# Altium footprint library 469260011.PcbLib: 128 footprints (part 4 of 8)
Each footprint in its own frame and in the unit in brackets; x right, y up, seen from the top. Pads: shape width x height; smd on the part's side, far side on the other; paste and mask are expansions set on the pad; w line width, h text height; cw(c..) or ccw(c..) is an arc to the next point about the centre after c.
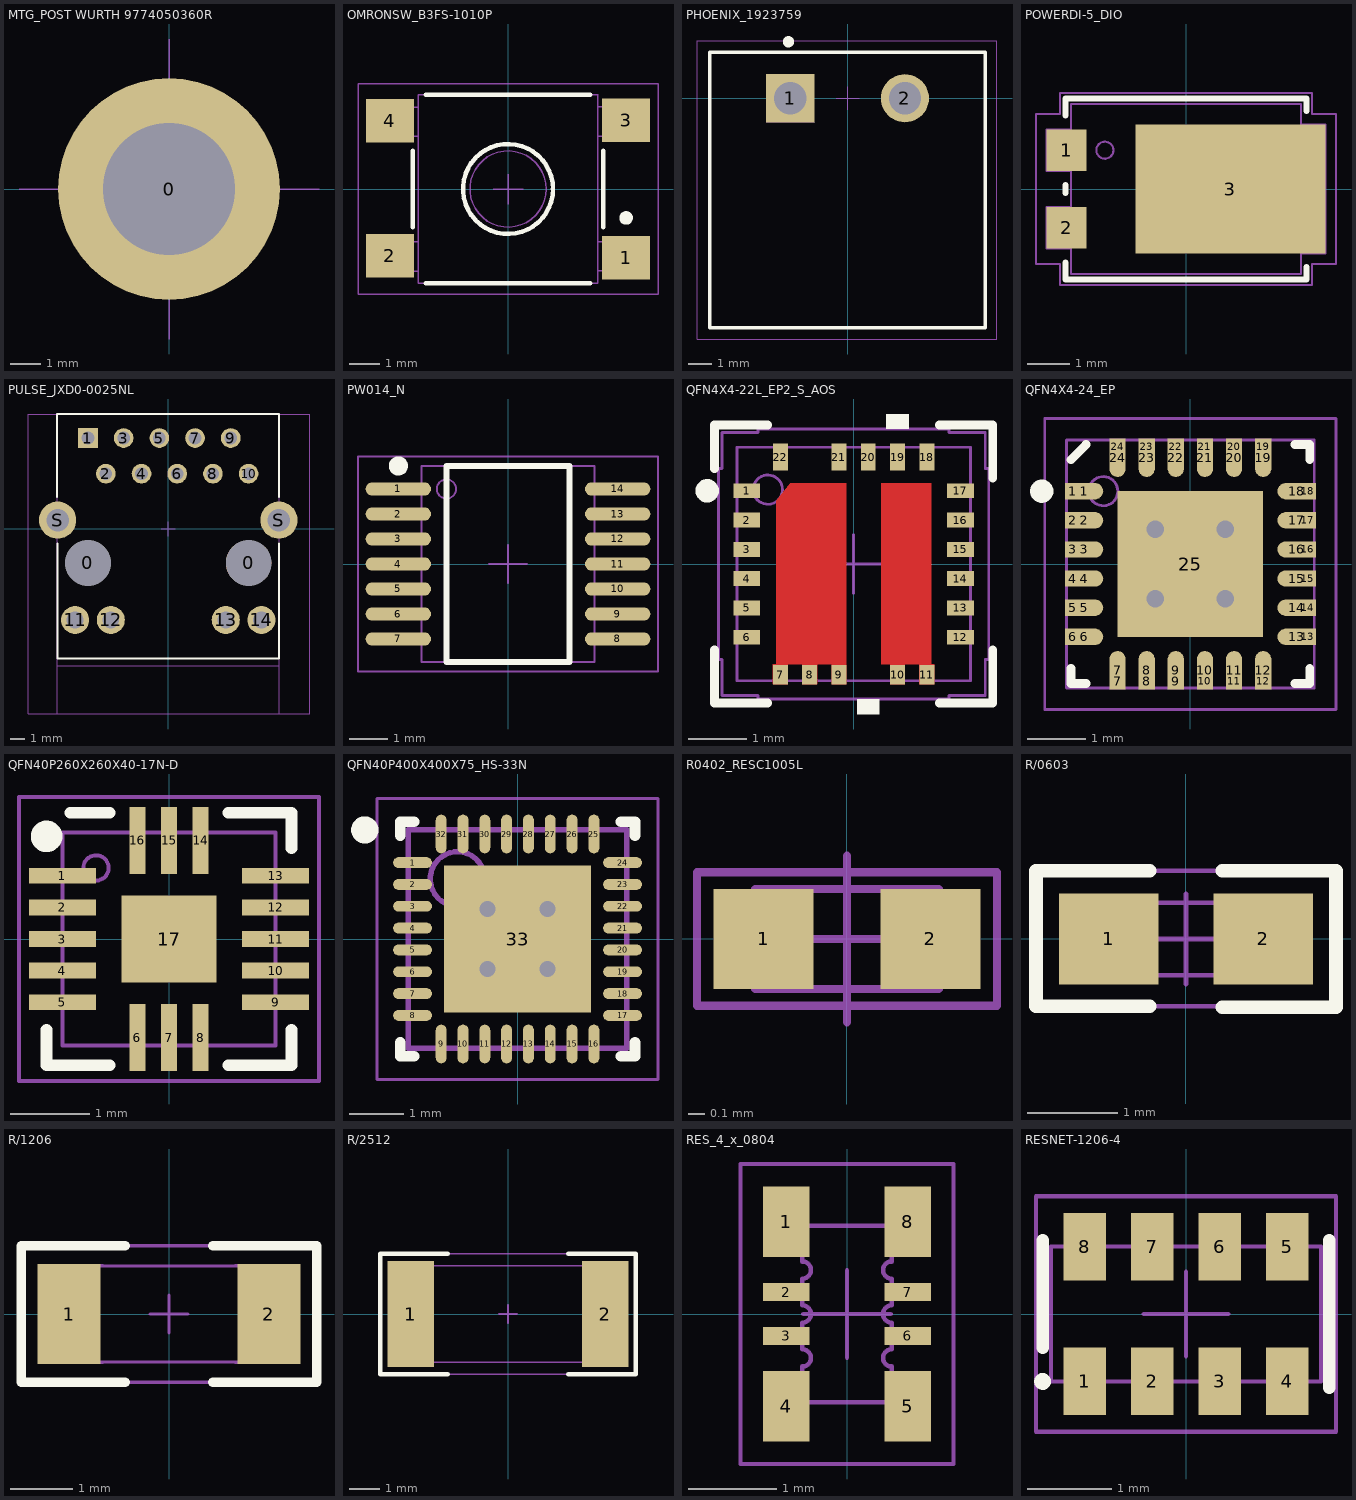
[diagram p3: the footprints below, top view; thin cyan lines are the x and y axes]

## MTG_POST WURTH 9774050360R [mm] "Mounting Post Wurth Electronics 9774050360R"
height 5
pads (1):
  round 7.4 hole 4.4: 0(0,0)
Top Paste:
  region: 3.61,-0.289 3.571,-0.596 3.395,-1.19 3.127,-1.748 2.772,-2.256 2.341,-2.7 1.844,-3.07 1.294,-3.356 0.706,-3.549 0.4,-3.598 0.4,-2.299 0.582,-2.263 0.934,-2.147 1.261,-1.975 1.556,-1.75 1.809,-1.479 2.013,-1.17 2.163,-0.831 2.255,-0.472 2.279,-0.289
  region: 0.4,3.594 0.693,3.548 1.258,3.368 1.79,3.104 2.274,2.761 2.7,2.348 3.057,1.874 3.338,1.351 3.535,0.792 3.589,0.5 2.281,0.5 2.241,0.667 2.123,0.99 1.956,1.291 1.744,1.562 1.494,1.797 1.21,1.991 0.899,2.139 0.569,2.237 0.4,2.266
  region: -3.614,0.25 -3.578,0.56 -3.407,1.162 -3.141,1.728 -2.788,2.243 -2.355,2.694 -1.856,3.07 -1.302,3.36 -0.709,3.557 -0.4,3.607 -0.4,2.299 -0.584,2.263 -0.94,2.145 -1.272,1.968 -1.568,1.738 -1.822,1.462 -2.026,1.147 -2.174,0.802 -2.261,0.437 -2.281,0.25
  region: -0.35,-3.609 -0.647,-3.566 -1.22,-3.39 -1.759,-3.126 -2.25,-2.782 -2.682,-2.367 -3.045,-1.889 -3.329,-1.361 -3.528,-0.795 -3.583,-0.5 -2.275,-0.5 -2.235,-0.671 -2.114,-0.999 -1.944,-1.305 -1.727,-1.58 -1.47,-1.818 -1.179,-2.013 -0.86,-2.159 -0.523,-2.253 -0.35,-2.28
Mechanical 1:
  lines w0.05: -5,0 5,0 ; 0,-5 0,5
3D body "9774050360R (rev1).stp": height 5, standoff -1.4, extent -3,-2.997 2.988,2.997

## OMRONSW_B3FS-1010P [mil] "SWITCH TACTILE SPST-NO 6.30mm x 6.00mm"
height 169.29
pads (4):
  rect 63x57 smd: 1(155,-90) 2(-154.96,-87.6) 3(155,90) 4(-154.96,89.57)
Top Overlay:
  circle w9.84: c155,-38 r3.94
  circle w5.91: c0,0 r59.06
  lines w5.91: -125,-50 -125,50 ; -108.27,-124.02 108.27,-124.02 ; -108.27,124.02 108.27,124.02 ; 125,-50 125,50
Top Assembly:
  circle w1.97: c0.07,0 r50.06
  lines w1.97: -118.11,123.58 -118.11,-124.02 118.11,-124.02 118.11,123.58 ; -118.04,-107.64 -165.28,-107.64 -165.28,-69.36 -118.04,-69.36 ; -118.07,68.93 -165.31,68.93 -165.31,107.2 -118.07,107.2 ; -118.07,123.58 118.15,123.58 ; 118.11,69.36 165.35,69.36 165.35,107.64 118.11,107.64 ; 118.14,-107.2 165.38,-107.2 165.38,-68.93 118.14,-68.93
  text ".Designator" at -88.6,-8.9 h39.37
Top Courtyard:
  lines w1.97: -19.61,0 19.76,0 ; 0,-19.69 0,19.68 ; -196.85,-137.8 -196.85,137.8 196.85,137.8 196.85,-137.8 -196.85,-137.8
3D body "Unnamed-B3FS_1000.step": height 118.11, standoff -3.94, extent -157.41,-124.02 157.55,124.02

## PHOENIX_1923759 [mm] "TERM BLOCK HDR 2POS 90DEG 5MM"
height 8.61
pads (2):
  rect 2.1x2.1 / inner round 2.1 / far side rect 2.1x2.1 hole 1.4: 1(-2.5,0)
  round 2.1 hole 1.4: 2(2.5,0)
Top Overlay:
  circle w0.25: c-2.576,2.464 r0.12
  lines w0.15: -6,-10 -6,2 6,2 6,-10 -6,-10
Top Assembly:
  region: -2.5,0 -1.45,-1.05 -3.55,-1.05
  lines w0.05: -6,-10 -6,2 6,2 6,-10 -6,-10
  text ".Designator" at -2.252,-0.226 h1
Top Courtyard:
  lines w0.05: -0.5,0 0.5,0 ; 0,-0.5 0,0.5 ; -6.55,-10.486 6.5,-10.486 6.5,2.514 -6.55,2.514 -6.55,-10.486
3D body "pxc_1923759_02_MSTBA-2-5-HC-2-G_3D.stp": height 9.14, standoff -2.96, extent -6,-10 6,2

## POWERDI-5_DIO [mil] "Diodes PowerDI5"
height 45.28
pads (3):
  rect 37x39 smd paste+0 mask+0: 1(-111.5,36.22) 2(-111.5,-36.22)
  rect 177x120 smd paste+0 mask+0: 3(41.5,0)
Top Overlay:
  lines w5.91: -112.5,-68.82 -112.5,-84.5 112.5,-84.5 112.5,-73.1 ; -112.5,-3.62 -112.5,3.62 ; -112.5,68.82 -112.5,84.5 112.5,84.5 112.5,73.1
Top 3D Body:
  lines w1: -107.5,-79.5 -107.5,79.5 107.5,79.5 107.5,-79.5 -107.5,-79.5
Top Assembly:
  circle w1.97: c-75.7,36.22 r7.95
  lines w1.97: -107.48,-55.7 -130,-55.7 -130,-16.73 -107.48,-16.73 ; -107.48,16.74 -130,16.74 -130,55.71 -107.48,55.71 ; 107.48,-60 130,-60 130,60 107.48,60 ; -107.48,-79.48 -107.48,79.49 107.48,79.49 107.48,-79.48 -107.48,-79.48
  text ".Designator" at -88.67,-8.9 h39.37
Top Courtyard:
  lines w1.97: -19.68,0 19.69,0 ; 0,-19.69 0,19.68 ; -140,-70 -117.5,-70 -117.5,-89.5 117.5,-89.5 117.5,-70 140,-70 140,70 117.5,70 117.5,89.5 -117.5,89.5 -117.5,70 -140,70 -140,-70
3D body "2x1_POWERDI-5_SBRT10U50SP5_DIO.step": height 45.24, standoff 0, extent -130,-79.49 130,79.49

## PULSE_JXD0-0025NL [mm]
height 13.63
pads (18):
  round 3.25 hole 3.25 unplated: 0(-5.715,-2.415) 0(5.715,-2.415)
  rect 1.4x1.4 hole 0.9: 1(-5.715,6.475)
  round 1.4 hole 0.9: 2(-4.445,3.935) 3(-3.175,6.475) 4(-1.905,3.935) 5(-0.635,6.475) 6(0.635,3.935) 7(1.905,6.475) 8(3.175,3.935) 9(4.445,6.475) 10(5.715,3.935)
  round 2 hole 1.2: 11(-6.63,-6.475) 12(-4.09,-6.475) 13(4.09,-6.475) 14(6.63,-6.475)
  round 2.65 hole 1.6: S(-7.875,0.635) S(7.875,0.635)
Top Overlay:
  lines w0.15: -7.915,2.285 -7.915,8.184 7.885,8.184 7.885,2.285 ; -7.885,-1.043 -7.885,-9.215 7.885,-9.215 7.885,-1.043
Mechanical 1:
  lines w0.05: -7.915,-9.715 7.885,-9.715 ; -7.915,-9.715 -7.915,-13.166 7.885,-13.166 7.885,-9.715 ; -7.915,-9.715 7.885,-9.715 ; -7.915,-9.715 7.885,-9.715
  text "KEEP-OUT" at -4.567,-12.094 h2
Top Assembly:
  lines w0.05: -7.915,-9.715 7.885,-9.715 ; -7.915,-13.166 7.885,-13.166 7.885,8.184 -7.915,8.184 -7.915,-13.166
  text ".Designator" at -2.252,-0.226 h1
Top Courtyard:
  lines w0.05: -0.5,0 0.5,0 ; 0,-0.5 0,0.5 ; -9.949,-13.166 10.051,-13.166 10.051,8.184 -9.949,8.184 -9.949,-13.166
3D body "JXD0-0025NL_3D.STEP": height 15.5, standoff -3.8, extent -9.949,-13.166 10.051,8.184

## PW014_N [mm] "TSOP, 14-Leads, Body 5x4.4mm, Pitch 0.65mm, IPC Medium Density"
height 1.2
pads (14):
  oval 1.7x0.35 smd: 1(-2.85,1.95) 2(-2.85,1.3) 3(-2.85,0.65) 4(-2.85,0) 5(-2.85,-0.65) 6(-2.85,-1.3) 7(-2.85,-1.95) 8(2.85,-1.95) 9(2.85,-1.3) 10(2.85,-0.65) 11(2.85,0) 12(2.85,0.65) 13(2.85,1.3) 14(2.85,1.95)
Top Overlay:
  circle w0.25: c-2.85,2.55 r0.125
  lines w0.15: -1.6,-2.55 -1.6,2.55 1.6,2.55 1.6,-2.55 -1.6,-2.55
Top Assembly:
  circle w0.05: c-1.6,1.95 r0.25
  lines w0.05: -2.25,-2.55 -2.25,2.55 2.25,2.55 2.25,-2.55 -2.25,-2.55
  text ".Designator" at -2.252,-0.226 h1
Top Courtyard:
  lines w0.05: -0.5,0 0.5,0 ; 0,-0.5 0,0.5 ; -3.9,-2.8 -3.9,2.8 3.9,2.8 3.9,-2.8 -3.9,-2.8
3D body "User Library-TSSOP14-1.step": height 1.1, standoff 0, extent -3.19,-2.493 3.21,2.507

## QFN4X4-22L_EP2_S_AOS [mil]
height 39.37
pads (22):
  rect 18x10 smd paste+0 mask+0: 1(-71.85,49.25) 2(-71.85,29.55) 3(-71.85,9.85) 4(-71.85,-9.85) 5(-71.85,-29.55) 6(-71.85,-49.25) 12(71.85,-49.25) 13(71.85,-29.55) 14(71.85,-9.85) 15(71.85,9.85) 16(71.85,29.55) 17(71.85,49.25)
  rect 10x13 smd paste-6.5 mask-6.5: 7(-49.25,-74.35) 8(-29.55,-74.35) 9(-9.85,-74.35) 10(29.55,-74.35) 11(49.25,-74.35)
  rect 10x18 smd paste+0 mask+0: 18(49.25,71.85) 19(29.55,71.85) 20(9.85,71.85) 21(-9.85,71.85) 22(-49.25,71.85)
Top Layer:
  region: 18.55,54.45 18.55,-67.55 24.55,-67.55 24.55,-80.85 34.55,-80.85 34.55,-67.55 44.25,-67.55 44.25,-80.85 54.25,-80.85 54.25,-67.55 52.25,-67.55 52.25,54.45
  region: -44.25,-80.85 -54.25,-80.85 -54.25,-67.55 -51.85,-67.55 -51.85,42.5 -42.5,54.45 -4.85,54.45 -4.85,-80.85 -14.85,-80.85 -14.85,-67.55 -24.55,-67.55 -24.55,-80.85 -34.55,-80.85 -34.55,-67.55 -44.25,-67.55
Top Overlay:
  circle w7.87: c-98.43,49.21 r3.94
  region: 37.05,90.85 22.05,90.85 22.05,100.85 37.05,100.85
  region: 17.35,-90.85 2.35,-90.85 2.35,-100.85 17.35,-100.85
  lines w5.91: -93.5,-57.66 -93.5,-93.5 -57.65,-93.5 ; -93.5,64.25 -93.5,93.5 -57.65,93.5 ; 57.65,-93.5 93.5,-93.5 93.5,-57.66 ; 57.65,93.5 93.5,93.5 93.5,57.66
Top Paste:
  region: 18.55,54.45 18.55,-67.55 24.55,-67.55 24.55,-80.85 34.55,-80.85 34.55,-67.55 44.25,-67.55 44.25,-80.85 54.25,-80.85 54.25,-67.55 52.25,-67.55 52.25,54.45
  region: -44.25,-80.85 -54.25,-80.85 -54.25,-67.55 -51.85,-67.55 -51.85,42.5 -42.5,54.45 -4.85,54.45 -4.85,-80.85 -14.85,-80.85 -14.85,-67.55 -24.55,-67.55 -24.55,-80.85 -34.55,-80.85 -34.55,-67.55 -44.25,-67.55
Top Solder:
  region: 18.55,54.45 18.55,-67.55 24.55,-67.55 24.55,-80.85 34.55,-80.85 34.55,-67.55 44.25,-67.55 44.25,-80.85 54.25,-80.85 54.25,-67.55 52.25,-67.55 52.25,54.45
  region: -44.25,-80.85 -54.25,-80.85 -54.25,-67.55 -51.85,-67.55 -51.85,42.5 -42.5,54.45 -4.85,54.45 -4.85,-80.85 -14.85,-80.85 -14.85,-67.55 -24.55,-67.55 -24.55,-80.85 -34.55,-80.85 -34.55,-67.55 -44.25,-67.55
Top Assembly:
  circle w1.97: c-57.65,50 r9.84
  lines w1.97: -78.5,-78.5 78.5,-78.5 78.5,78.5 -78.5,78.5 -78.5,-78.5
  text ".Designator" at -88.67,-8.9 h39.37
Top Courtyard:
  lines w1.97: -19.68,0 19.69,0 ; 0,-19.69 0,19.68 ; -90.85,-64.25 -88.5,-64.25 -88.5,-88.5 -64.25,-88.5 -64.25,-90.85 64.25,-90.85 64.25,-88.5 88.5,-88.5 88.5,-64.25 90.85,-64.25 90.85,64.25 88.5,64.25 88.5,88.5 64.25,88.5 64.25,90.85 -64.25,90.85 -64.25,88.5 -88.5,88.5 -88.5,64.25 -90.85,64.25 -90.85,-64.25
3D body "User Library-QFN-24 - EQ.step": height 39.37, standoff 0, extent -78.74,-78.74 78.74,78.74

## QFN4X4-24_EP [mm] "24-VQFN (4x4), 24-VFQFN Exposed Pad, Quad Flat No Lead, Plastic; 24 Terminals; Body 4 x 4 mm; Pitch 0.5 mm"
height 0.8
pads (49):
  rect 0.28x0.28 smd: 1(-2.015,1.25) 2(-2.015,0.75) 3(-2.015,0.25) 4(-2.015,-0.25) 5(-2.015,-0.75) 6(-2.015,-1.25) 7(-1.25,-2.015) 8(-0.75,-2.015) 9(-0.25,-2.015) 10(0.25,-2.015) 11(0.75,-2.015) 12(1.25,-2.015) 13(2.015,-1.25) 14(2.015,-0.75) 15(2.015,-0.25) 16(2.015,0.25) 17(2.015,0.75) 18(2.015,1.25) 19(1.25,2.015) 20(0.75,2.015) 21(0.25,2.015) 22(-0.25,2.015) 23(-0.75,2.015) 24(-1.25,2.015)
  oval 0.66x0.28 smd: 1(-1.825,1.25) 2(-1.825,0.75) 3(-1.825,0.25) 4(-1.825,-0.25) 5(-1.825,-0.75) 6(-1.825,-1.25) 13(1.825,-1.25) 14(1.825,-0.75) 15(1.825,-0.25) 16(1.825,0.25) 17(1.825,0.75) 18(1.825,1.25)
  oval 0.28x0.66 smd: 7(-1.25,-1.825) 8(-0.75,-1.825) 9(-0.25,-1.825) 10(0.25,-1.825) 11(0.75,-1.825) 12(1.25,-1.825) 19(1.25,1.825) 20(0.75,1.825) 21(0.25,1.825) 22(-0.25,1.825) 23(-0.75,1.825) 24(-1.25,1.825)
  rect 2.5x2.5 smd: 25(0,0)
via -0.6,0.6 diameter 0.6 hole 0.3
via 0.6,0.6 diameter 0.6 hole 0.3
via -0.6,-0.6 diameter 0.6 hole 0.3
via 0.6,-0.6 diameter 0.6 hole 0.3
Top Overlay:
  circle w0.2: c-2.55,1.25 r0.1
  lines w0.15: -2.05,-1.79 -2.05,-2.05 -1.79,-2.05 ; -2.05,1.79 -1.79,2.05 ; 1.79,-2.05 2.05,-2.05 2.05,-1.79 ; 1.79,2.05 2.05,2.05 2.05,1.79
Top Assembly:
  circle w0.05: c-1.495,1.25 r0.25
  lines w0.05: -2.126,-2.126 -2.126,2.126 2.126,2.126 2.126,-2.126 -2.126,-2.126
  text ".Designator" at -2.252,-0.226 h1
Top Courtyard:
  lines w0.05: -0.5,0 0.5,0 ; 0,-0.5 0,0.5 ; -2.5,-2.5 -2.5,2.5 2.5,2.5 2.5,-2.5 -2.5,-2.5
3D body "RGE24_2P7X2P7_TEX.step": height 1, standoff 0, extent -2.126,-2.126 2.126,2.126

## QFN40P260X260X40-17N-D [mm] "16-HX2QFN (2.6x2.6), 16-XFQFN Exposed Pad"
height 0.4
pads (17):
  rect 0.85x0.2 smd: 1(-1.35,0.8) 2(-1.35,0.4) 3(-1.35,0) 4(-1.35,-0.4) 5(-1.35,-0.8) 9(1.35,-0.8) 10(1.35,-0.4) 11(1.35,0) 12(1.35,0.4) 13(1.35,0.8)
  rect 0.2x0.85 smd: 6(-0.4,-1.25) 7(0,-1.25) 8(0.4,-1.25) 14(0.4,1.25) 15(0,1.25) 16(-0.4,1.25)
  rect 1.2x1.1 smd: 17(0,0)
Top Overlay:
  circle w0.2: c-1.55,1.3 r0.1
  lines w0.15: -1.55,-1.15 -1.55,-1.6 -0.75,-1.6 ; -1.25,1.6 -0.75,1.6 ; 0.75,-1.6 1.55,-1.6 1.55,-1.15 ; 0.75,1.6 1.55,1.6 1.55,1.15
Top Assembly:
  circle w0.05: c-0.925,0.9 r0.16
  lines w0.05: -1.35,-1.35 1.35,-1.35 1.35,1.35 -1.35,1.35 -1.35,-1.35
  text ".Designator" at -2.252,-0.226 h1
Top Courtyard:
  lines w0.05: -0.5,0 0.5,0 ; 0,-0.5 0,0.5 ; -1.9,-1.8 -1.9,1.8 1.9,1.8 1.9,-1.8 -1.9,-1.8
3D body "PTN5110NHQZ.stp": height 0.4, standoff 0, extent -1.346,-1.346 1.354,1.354

## QFN40P400X400X75_HS-33N [mm] "QFN, 32-Leads, Body 4,00x4,00mm, Pitch 0,40mm, Thermal Pad 2,70x2,70mm, IPC Medium Density"
height 0.75
pads (33):
  oval 0.711x0.2 smd: 1(-1.925,1.4) 2(-1.925,1) 3(-1.925,0.6) 4(-1.925,0.2) 5(-1.925,-0.2) 6(-1.925,-0.6) 7(-1.925,-1) 8(-1.925,-1.4) 17(1.925,-1.4) 18(1.925,-1) 19(1.925,-0.6) 20(1.925,-0.2) 21(1.925,0.2) 22(1.925,0.6) 23(1.925,1) 24(1.925,1.4)
  oval 0.2x0.711 smd: 9(-1.4,-1.925) 10(-1,-1.925) 11(-0.6,-1.925) 12(-0.2,-1.925) 13(0.2,-1.925) 14(0.6,-1.925) 15(1,-1.925) 16(1.4,-1.925) 25(1.4,1.925) 26(1,1.925) 27(0.6,1.925) 28(0.2,1.925) 29(-0.2,1.925) 30(-0.6,1.925) 31(-1,1.925) 32(-1.4,1.925)
  rect 2.7x2.7 smd: 33(0,0)
via -0.55,0.55 diameter 0.6 hole 0.3
via 0.55,0.55 diameter 0.6 hole 0.3
via -0.55,-0.55 diameter 0.6 hole 0.3
via 0.55,-0.55 diameter 0.6 hole 0.3
Top Overlay:
  circle w0.25: c-2.8,2 r0.125
  lines w0.2: -2.15,-1.9 -2.15,-2.15 -1.9,-2.15 ; -2.15,1.9 -2.15,2.15 -1.9,2.15 ; 1.9,-2.15 2.15,-2.15 2.15,-1.9 ; 1.9,2.15 2.15,2.15 2.15,1.9
Top 3D Body:
  circle w0.1: c-1.1,1.1 r0.5
  lines w0.1: -2,-2 -2,2 2,2 2,-2 -2,-2
Top Courtyard:
  lines w0.05: -2.575,-2.575 -2.575,2.575 2.575,2.575 2.575,-2.575 -2.575,-2.575
  lines w0.1: -0.5,0 0.5,0 ; 0,-0.5 0,0.5
3D body "QFN32_4X4X0P75_CIR.step": height 0.81, standoff 0, extent -1.994,-1.994 1.994,1.994

## R0402_RESC1005L [mm] "Chip Resistor, Body 1.1x0.5mm, IPC High Density"
height 0.4
pads (2):
  rect 0.6x0.6 smd: 1(-0.5,0) 2(0.5,0)
Top Assembly:
  lines w0.05: -0.55,-0.3 0.55,-0.3 0.55,0.3 -0.55,0.3 -0.55,-0.3
  text ".Designator" at -2.252,-0.226 h1
Top Courtyard:
  lines w0.05: -0.5,0 0.5,0 ; 0,-0.5 0,0.5 ; -0.9,-0.4 -0.9,0.4 0.9,0.4 0.9,-0.4 -0.9,-0.4
3D body "User Library-User Library-RES0402-2.step": height 0.35, standoff 0, extent -0.5,-0.25 0.5,0.25

## R/0603 [mm]
height 14
pads (2):
  rect 1.1x1 smd: 1(-0.85,0) 2(0.85,0)
Top Overlay:
  lines w0.15: -0.4,-0.739 -1.651,-0.739 -1.651,0.75 -0.4,0.75 ; 0.4,-0.75 1.651,-0.75 1.651,0.75 0.4,0.75
Top Assembly:
  lines w0.05: -0.8,-0.4 0.8,-0.4 0.8,0.4 -0.8,0.4 -0.8,-0.4
  text ".Designator" at -2.252,-0.226 h1
Top Courtyard:
  lines w0.05: -0.5,0 0.5,0 ; 0,-0.5 0,0.5 ; -1.651,-0.739 1.651,-0.739 1.651,0.75 -1.651,0.75 -1.651,-0.739
3D body "User Library-CR1608-0603.step": height 0.45, standoff 0, extent -0.8,-0.4 0.8,0.4

## R/1206 [mm] "1206 (3216 Metric)"
height 0.7
pads (2):
  rect 1x1.6 smd: 1(-1.6,0) 2(1.6,0)
Top Overlay:
  lines w0.15: -0.7,-1.092 -2.362,-1.092 -2.362,1.092 -0.7,1.092 ; 0.7,-1.092 2.362,-1.092 2.362,1.092 0.7,1.092
Top Assembly:
  lines w0.05: -1.505,-0.765 ccw(c-1.495,-0.765) -1.495,-0.775 ; -1.505,-0.765 -1.505,0.765 ; -1.505,-0.765 -1.495,-0.765 ; -1.505,0.765 cw(c-1.495,0.765) -1.495,0.775 ; -1.505,0.765 -1.495,0.765 ; -1.495,-0.775 -1.165,-0.775 ; -1.495,-0.775 -1.495,-0.765 ; -1.495,-0.765 -1.165,-0.765 ; -1.495,-0.765 -1.495,0.765 ; -1.495,0.765 -1.495,0.775 ; -1.495,0.765 -1.165,0.765 ; -1.495,0.775 -1.165,0.775 ; -1.165,-0.775 ccw(c-1.165,-0.765) -1.155,-0.765 ; -1.165,-0.775 -1.065,-0.775 ccw(c-1.065,-0.765) -1.055,-0.765 ; -1.165,-0.775 -1.165,-0.765 ; -1.165,-0.765 -1.155,-0.765 ; -1.165,0.765 -1.165,0.775 ; -1.165,0.765 -1.155,0.765 ; -1.165,0.775 cw(c-1.165,0.765) -1.155,0.765 ; -1.165,0.775 -1.065,0.775 cw(c-1.065,0.765) -1.055,0.765 ; -1.155,-0.765 -1.085,-0.765 -1.055,-0.765 ; -1.155,0.765 -1.085,0.765 -1.055,0.765 ; -1.055,-0.765 1.055,-0.765 ; -1.055,0.765 1.055,0.765 ; 1.055,-0.765 ccw(c1.065,-0.765) 1.065,-0.775 1.165,-0.775 ; 1.055,-0.765 1.085,-0.765 1.155,-0.765 ; 1.055,0.765 cw(c1.065,0.765) 1.065,0.775 1.165,0.775 ; 1.055,0.765 1.085,0.765 1.155,0.765 ; 1.155,-0.765 ccw(c1.165,-0.765) 1.165,-0.775 ; 1.155,-0.765 1.165,-0.765 ; 1.155,0.765 cw(c1.165,0.765) 1.165,0.775 ; 1.155,0.765 1.165,0.765 ; 1.165,-0.775 1.495,-0.775 ; 1.165,-0.775 1.165,-0.765 ; 1.165,-0.765 1.495,-0.765 ; 1.165,0.765 1.495,0.765 ; 1.165,0.765 1.165,0.775 ; 1.165,0.775 1.495,0.775 ; 1.495,-0.775 ccw(c1.495,-0.765) 1.505,-0.765 ; 1.495,-0.775 1.495,-0.765 ; 1.495,-0.765 1.505,-0.765 ; 1.495,-0.765 1.495,0.765 ; 1.495,0.765 1.495,0.775 ; 1.495,0.765 1.505,0.765 ; 1.495,0.775 cw(c1.495,0.765) 1.505,0.765 ; 1.505,-0.765 1.505,0.765
  text ".Designator" at -2.252,-0.226 h1
Top Courtyard:
  lines w0.05: -0.3,0 0.3,0 ; 0,-0.3 0,0.3 ; -2.362,-1.092 -2.362,1.092 2.362,1.092 2.362,-1.092 -2.362,-1.092
3D body "User Library-RES1206-2.step": height 0.55, standoff 0, extent -1.505,-0.775 1.505,0.775

## R/2512 [mm] "2512 (6432 Metric)"
height 0.7
pads (2):
  rect 1.55x3.5 smd: 1(-3.225,0) 2(3.225,0)
Top Overlay:
  lines w0.15: -2,-2 -4.242,-2 -4.242,2 -2,2 ; 2,-2 4.242,-2 4.242,2 2,2
Top Assembly:
  lines w0.05: -2.523,-1.599 -2.49,-1.599 ; -2.523,1.6 -2.49,1.6 ; -2.49,-1.6 -2.46,-1.6 2.46,-1.6 2.49,-1.6 ; -2.49,1.6 -2.46,1.6 2.46,1.6 2.49,1.6 ; 2.49,-1.599 2.523,-1.599 ; 2.49,1.6 2.523,1.6 ; -3.2,-1.595 ccw(c-3.195,-1.595) -3.195,-1.6 ; -3.2,-1.595 -3.195,-1.595 ; -3.2,-1.595 -3.2,1.595 ; -3.2,1.595 cw(c-3.195,1.595) -3.195,1.6 ; -3.2,1.595 -3.195,1.595 ; -3.195,-1.6 -3.195,-1.595 ; -3.195,-1.6 -2.525,-1.6 ; -3.195,-1.595 -2.525,-1.595 ; -3.195,-1.595 -3.195,1.595 ; -3.195,1.595 -3.195,1.6 ; -3.195,1.595 -2.525,1.595 ; -3.195,1.6 -2.525,1.6 ; -2.525,-1.6 ccw(c-2.525,-1.595) -2.52,-1.595 -2.525,-1.595 ; -2.525,-1.6 -2.525,-1.595 ; -2.525,1.595 -2.525,1.6 ; -2.525,1.595 -2.52,1.595 ccw(c-2.525,1.595) -2.525,1.6 ; 2.525,-1.6 cw(c2.525,-1.595) 2.52,-1.595 2.525,-1.595 ; 2.525,-1.6 2.525,-1.595 ; 2.525,-1.6 3.195,-1.6 ; 2.525,-1.595 3.195,-1.595 ; 2.525,1.595 2.525,1.6 ; 2.525,1.595 3.195,1.595 ; 2.525,1.595 2.52,1.595 cw(c2.525,1.595) 2.525,1.6 ; 2.525,1.6 3.195,1.6 ; 3.195,-1.6 ccw(c3.195,-1.595) 3.2,-1.595 ; 3.195,-1.6 3.195,-1.595 ; 3.195,-1.595 3.195,1.595 ; 3.195,-1.595 3.2,-1.595 ; 3.195,1.595 3.195,1.6 ; 3.195,1.595 3.2,1.595 ; 3.195,1.6 cw(c3.195,1.595) 3.2,1.595 ; 3.2,-1.595 3.2,1.595
  text ".Designator" at -2.252,-0.226 h1
Top Courtyard:
  lines w0.05: -0.3,0 0.3,0 ; 0,-0.3 0,0.3 ; -4.242,-2 -4.242,2 4.242,2 4.242,-2 -4.242,-2
3D body "User Library-RESC6432X06.step": height 0.6, standoff 0, extent -3.2,-1.6 3.2,1.6

## RES_4_x_0804 [mm] "RES ARR 4 RES 22 OHM 0804"
height 0.5
pads (8):
  rect 0.532x0.806 smd paste+0 mask+0: 1(-0.692,1.05) 4(-0.692,-1.05) 5(0.692,-1.05) 8(0.692,1.05)
  rect 0.532x0.205 smd paste+0 mask-0.025: 2(-0.692,0.25) 3(-0.692,-0.25) 6(0.692,-0.25) 7(0.692,0.25)
Top Assembly:
  lines w0.05: -0.508,0.597 -0.508,1.003 0.508,1.003 0.508,0.597 ; -0.508,0.598 cw(c-0.508,0.5) -0.508,0.402 -0.508,0.098 cw(c-0.508,0) -0.508,-0.098 -0.508,-0.402 cw(c-0.508,-0.5) -0.508,-0.598 -0.508,-0.597 -0.508,-1.003 0.508,-1.003 0.508,-0.597 0.508,-0.598 cw(c0.508,-0.5) 0.508,-0.402 0.508,-0.098 cw(c0.508,0) 0.508,0.098 0.508,0.402 cw(c0.508,0.5) 0.508,0.598
  text ".Designator" at -2.252,-0.226 h1
Top Courtyard:
  lines w0.05: -0.5,0 0.5,0 ; 0,-0.5 0,0.5 ; -1.212,-1.707 -1.212,1.707 1.212,1.707 1.212,-1.707 -1.212,-1.707
3D body "BO_CAY10.step": height 0.36, standoff 0, extent -0.508,-1.003 0.508,1.003

## RESNET-1206-4 [mm]
pads (8):
  rect 0.5x0.8 smd: 1(-1.2,-0.8) 2(-0.4,-0.8) 3(0.4,-0.8) 4(1.2,-0.8) 5(1.2,0.8) 6(0.4,0.8) 7(-0.4,0.8) 8(-1.2,0.8)
Top Overlay:
  circle w0.1: c-1.7,-0.8 r0.05
  lines w0.15: -1.7,-0.4 -1.7,0.875 ; 1.7,-0.875 1.7,0.875
Top Assembly:
  lines w0.05: -1.6,-0.8 -1.6,0.8 1.6,0.8 1.6,-0.8 -1.6,-0.8
  text ".Designator" at -2.252,-0.226 h1
Top Courtyard:
  lines w0.05: -0.5,0 0.5,0 ; 0,-0.5 0,0.5 ; -1.778,-1.397 1.778,-1.397 1.778,1.397 -1.778,1.397 -1.778,-1.397
3D body "User Library-R1206-4R.step": height 0.57, standoff -0.01, extent -1.6,-0.8 1.6,0.8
